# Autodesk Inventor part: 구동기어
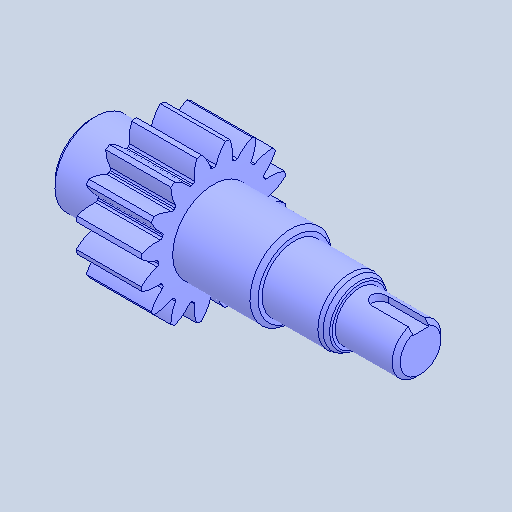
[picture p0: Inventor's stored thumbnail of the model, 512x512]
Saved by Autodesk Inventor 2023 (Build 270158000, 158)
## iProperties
Created: 2025-10
Part Number: 구동기어
Material: 강철, 합금
Document SubType Name: Modeling
Designer: home
Density: 7.73 g/cm^3
Appearance: 기본값
Author: jhkim
Sending System: Autodesk Inventor 2026
Preprocessor: ST-DEVELOPER v20.1
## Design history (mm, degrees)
feature "솔리드1"
node "솔리드2"
